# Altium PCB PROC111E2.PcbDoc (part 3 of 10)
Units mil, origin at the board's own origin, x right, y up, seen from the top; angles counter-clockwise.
Board outline 7700 x 2300 mil, 6 copper layers (Top Layer, GND 1, SIG 1, SIG 2, GND 2, Bottom Layer), stack 78.711 mil thick; 767 components, 596 nets, 2755 pads, 1578 vias.
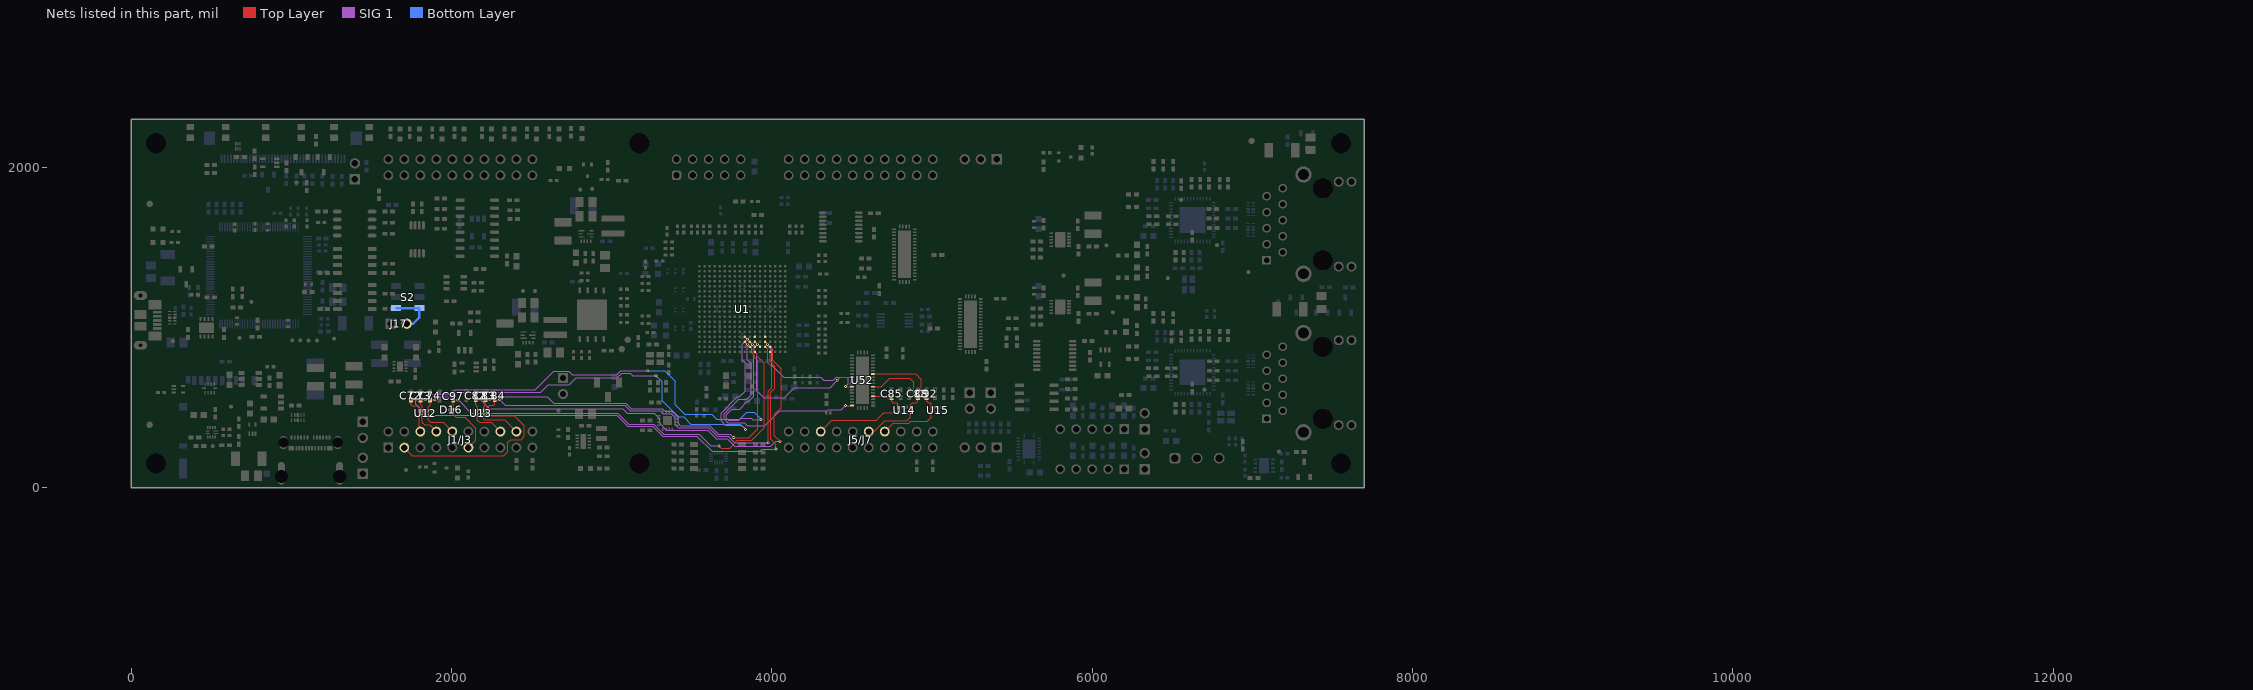
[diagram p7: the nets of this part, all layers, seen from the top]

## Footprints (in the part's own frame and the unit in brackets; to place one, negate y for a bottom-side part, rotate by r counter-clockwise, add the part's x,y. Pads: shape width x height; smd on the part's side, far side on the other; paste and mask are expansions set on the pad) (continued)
"ZCZ (S-PBGA-N324)" [mm] "0.8mm pitch, 15x15mm, Plastic Ball Grid Array"
  round 0.4 smd: A1(0,0) A2(0.8,0) A3(1.6,0) A4(2.4,0) A5(3.2,0) A6(4,0) A7(4.8,0) A8(5.6,0) A9(6.4,0) A10(7.2,0) A11(8,0) A12(8.8,0) A13(9.6,0) A14(10.4,0) A15(11.2,0) A16(12,0) A17(12.8,0) A18(13.6,0) B1(0,-0.8) B2(0.8,-0.8) B3(1.6,-0.8) B4(2.4,-0.8) B5(3.2,-0.8) B6(4,-0.8) B7(4.8,-0.8) B8(5.6,-0.8) B9(6.4,-0.8) B10(7.2,-0.8) B11(8,-0.8) B12(8.8,-0.8) B13(9.6,-0.8) B14(10.4,-0.8) B15(11.2,-0.8) B16(12,-0.8) B17(12.8,-0.8) B18(13.6,-0.8) C1(0,-1.6) C2(0.8,-1.6) C3(1.6,-1.6) C4(2.4,-1.6) C5(3.2,-1.6) C6(4,-1.6) C7(4.8,-1.6) C8(5.6,-1.6) C9(6.4,-1.6) C10(7.2,-1.6) C11(8,-1.6) C12(8.8,-1.6) C13(9.6,-1.6) C14(10.4,-1.6) C15(11.2,-1.6) C16(12,-1.6) C17(12.8,-1.6) C18(13.6,-1.6) D1(0,-2.4) D2(0.8,-2.4) D3(1.6,-2.4) D4(2.4,-2.4) D5(3.2,-2.4) D6(4,-2.4) D7(4.8,-2.4) D8(5.6,-2.4) D9(6.4,-2.4) D10(7.2,-2.4) D11(8,-2.4) D12(8.8,-2.4) D13(9.6,-2.4) D14(10.4,-2.4) D15(11.2,-2.4) D16(12,-2.4) D17(12.8,-2.4) D18(13.6,-2.4) E1(0,-3.2) E2(0.8,-3.2) E3(1.6,-3.2) E4(2.4,-3.2) E5(3.2,-3.2) E6(4,-3.2) E7(4.8,-3.2) E8(5.6,-3.2) E9(6.4,-3.2) E10(7.2,-3.2) E11(8,-3.2) E12(8.8,-3.2) E13(9.6,-3.2) E14(10.4,-3.2) E15(11.2,-3.2) E16(12,-3.2) E17(12.8,-3.2) E18(13.6,-3.2) F1(0,-4) F2(0.8,-4) F3(1.6,-4) F4(2.4,-4) F5(3.2,-4) F6(4,-4) F7(4.8,-4) F8(5.6,-4) F9(6.4,-4) F10(7.2,-4) F11(8,-4) F12(8.8,-4) F13(9.6,-4) F14(10.4,-4) F15(11.2,-4) F16(12,-4) F17(12.8,-4) F18(13.6,-4) G1(0,-4.8) G2(0.8,-4.8) G3(1.6,-4.8) G4(2.4,-4.8) G5(3.2,-4.8) G6(4,-4.8) G7(4.8,-4.8) G8(5.6,-4.8) G9(6.4,-4.8) G10(7.2,-4.8) G11(8,-4.8) G12(8.8,-4.8) G13(9.6,-4.8) G14(10.4,-4.8) G15(11.2,-4.8) G16(12,-4.8) G17(12.8,-4.8) G18(13.6,-4.8) H1(0,-5.6) H2(0.8,-5.6) H3(1.6,-5.6) H4(2.4,-5.6) H5(3.2,-5.6) H6(4,-5.6) H7(4.8,-5.6) H8(5.6,-5.6) H9(6.4,-5.6) H10(7.2,-5.6) H11(8,-5.6) H12(8.8,-5.6) H13(9.6,-5.6) H14(10.4,-5.6) H15(11.2,-5.6) H16(12,-5.6) H17(12.8,-5.6) H18(13.6,-5.6) J1(0,-6.4) J2(0.8,-6.4) J3(1.6,-6.4) J4(2.4,-6.4) J5(3.2,-6.4) J6(4,-6.4) J7(4.8,-6.4) J8(5.6,-6.4) J9(6.4,-6.4) J10(7.2,-6.4) J11(8,-6.4) J12(8.8,-6.4) J13(9.6,-6.4) J14(10.4,-6.4) J15(11.2,-6.4) J16(12,-6.4) J17(12.8,-6.4) J18(13.6,-6.4) K1(0,-7.2) K2(0.8,-7.2) K3(1.6,-7.2) K4(2.4,-7.2) K5(3.2,-7.2) K6(4,-7.2) K7(4.8,-7.2) K8(5.6,-7.2) K9(6.4,-7.2) K10(7.2,-7.2) K11(8,-7.2) K12(8.8,-7.2) K13(9.6,-7.2) K14(10.4,-7.2) K15(11.2,-7.2) K16(12,-7.2) K17(12.8,-7.2) K18(13.6,-7.2) L1(0,-8) L2(0.8,-8) L3(1.6,-8) L4(2.4,-8) L5(3.2,-8) L6(4,-8) L7(4.8,-8) L8(5.6,-8) L9(6.4,-8) L10(7.2,-8) L11(8,-8) L12(8.8,-8) L13(9.6,-8) L14(10.4,-8) L15(11.2,-8) L16(12,-8) L17(12.8,-8) L18(13.6,-8) M1(0,-8.8) M2(0.8,-8.8) M3(1.6,-8.8) M4(2.4,-8.8) M5(3.2,-8.8) M6(4,-8.8) M7(4.8,-8.8) M8(5.6,-8.8) M9(6.4,-8.8) M10(7.2,-8.8) M11(8,-8.8) M12(8.8,-8.8) M13(9.6,-8.8) M14(10.4,-8.8) M15(11.2,-8.8) M16(12,-8.8) M17(12.8,-8.8) M18(13.6,-8.8) N1(0,-9.6) N2(0.8,-9.6) N3(1.6,-9.6) N4(2.4,-9.6) N5(3.2,-9.6) N6(4,-9.6) N7(4.8,-9.6) N8(5.6,-9.6) N9(6.4,-9.6) N10(7.2,-9.6) N11(8,-9.6) N12(8.8,-9.6) N13(9.6,-9.6) N14(10.4,-9.6) N15(11.2,-9.6) N16(12,-9.6) N17(12.8,-9.6) N18(13.6,-9.6) P1(0,-10.4) P2(0.8,-10.4) P3(1.6,-10.4) P4(2.4,-10.4) P5(3.2,-10.4) P6(4,-10.4) P7(4.8,-10.4) P8(5.6,-10.4) P9(6.4,-10.4) P10(7.2,-10.4) P11(8,-10.4) P12(8.8,-10.4) P13(9.6,-10.4) P14(10.4,-10.4) P15(11.2,-10.4) P16(12,-10.4) P17(12.8,-10.4) P18(13.6,-10.4) R1(0,-11.2) R2(0.8,-11.2) R3(1.6,-11.2) R4(2.4,-11.2) R5(3.2,-11.2) R6(4,-11.2) R7(4.8,-11.2) R8(5.6,-11.2) R9(6.4,-11.2) R10(7.2,-11.2) R11(8,-11.2) R12(8.8,-11.2) R13(9.6,-11.2) R14(10.4,-11.2) R15(11.2,-11.2) R16(12,-11.2) R17(12.8,-11.2) R18(13.6,-11.2) T1(0,-12) T2(0.8,-12) T3(1.6,-12) T4(2.4,-12) T5(3.2,-12) T6(4,-12) T7(4.8,-12) T8(5.6,-12) T9(6.4,-12) T10(7.2,-12) T11(8,-12) T12(8.8,-12) T13(9.6,-12) T14(10.4,-12) T15(11.2,-12) T16(12,-12) T17(12.8,-12) T18(13.6,-12) U1(0,-12.8) U2(0.8,-12.8) U3(1.6,-12.8) U4(2.4,-12.8) U5(3.2,-12.8) U6(4,-12.8) U7(4.8,-12.8) U8(5.6,-12.8) U9(6.4,-12.8) U10(7.2,-12.8) U11(8,-12.8) U12(8.8,-12.8) U13(9.6,-12.8) U14(10.4,-12.8) U15(11.2,-12.8) U16(12,-12.8) U17(12.8,-12.8) U18(13.6,-12.8) V1(0,-13.6) V2(0.8,-13.6) V3(1.6,-13.6) V4(2.4,-13.6) V5(3.2,-13.6) V6(4,-13.6) V7(4.8,-13.6) V8(5.6,-13.6) V9(6.4,-13.6) V10(7.2,-13.6) V11(8,-13.6) V12(8.8,-13.6) V13(9.6,-13.6) V14(10.4,-13.6) V15(11.2,-13.6) V16(12,-13.6) V17(12.8,-13.6) V18(13.6,-13.6)
  silkscreen extent -0.8,-14.4 14.4,0.8, body extent -0.7,-14.3 14.3,0.7, height 1

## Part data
C1 C2 C3 C4 C5 C6 C14 C23 C25 C52 C53 C68 C236: library part CMP-0007057-4, "CAP, CERM, 3.3 uF, 10 V, +/- 10%, X7S, 0603", Cap_Case=0603, Manufacturer=TDK, Supplier Part Number 1=445-14256-1-ND, TempCo=X7S, Tolerance_%=10%, Value1="0.004796 ohm", Value2=10V, ValueDisplayed=3.3uF
C7 C8 C9 C10 C11 C12 C13 C15 C16 C17 C18 C24 C26 C27 C28 C34 C35 C36 C37 C38 C48 C69 C72 C73 C74 C75 C78 C79 C80 C81 C82 C83 C84 C85 C86 C87 C88 C90 C91 C92 C93 C94 C95 C96 C97 C98 C117 C119 C121 C125 C127 C131 C133 C165 C176 C194 C196 C198 C202 C204 C208 C210 C237: library part CMP-0006623-2, "CAP, CERM, 0.1 uF, 6.3 V, +/- 10%, X7R, 0402", Cap_Case=0402, Manufacturer=MuRata, Supplier Part Number 1=GRM155R70J104KA01D-ND, TempCo=X7R, Tolerance_%=10%, Value1=Unknown, Value2=6.3V, ValueDisplayed=0.1uF
C19 C20 C21 C22 C29 C30 C31 C32 C39 C40 C41 C42 C44 C45 C46 C47: library part CMP-0093721-1, "Chip Multilayer Ceramic Capacitors for General Purpose, 0201, 1.0uF, X6S, 22%, 20%, 6.3V", Manufacturer=Murata, Operating Temperature Range="-55°C to +105°C", TempCo=22%, Temperature Characteristic=X6S, Tolerance_%=20%, ValueDisplayed=1.0uF
C33 C76 C77 C89: library part CMP-0007498-4, "CAP, CERM, 4.7 uF, 10 V, +/- 20%, X7R, 0603", Cap_Case=0603, Manufacturer=MuRata, TempCo=X7R, Tolerance_%=20%, Value1=Unknown, Value2=10V, ValueDisplayed=4.7uF
C43 C57 C60 C61 C62 C64 C65 C66 C70 C71 C99 C100 C111 C134 C136 C137 C138 C139 C140 C141 C142 C145 C147 C150 C151 C154 C155 C163 C174 C181 C182 C183 C184 C186 C188 C223 C225 C226 C233 C238 C239 C240 C241 C242 C243 C244 C245 C246: library part CMP-0006659-2, "CAP, CERM, 0.1 uF, 25 V, +/- 10%, X7R, 0402", Cap_Case=0402, Manufacturer=MuRata, Supplier Part Number 1=490-10698-1-ND, TempCo=X7R, Tolerance_%=10%, Value1=Unknown, Value2=25V, ValueDisplayed=0.1uF
C49 C50 C51 C54 C55 C56: library part CMP-0064970-1, "CAP, CERM, 0.1 uF, 16 V,+/- 10%, X7R, 0201", Cap_Case=0201, Manufacturer=MuRata, Supplier Part Number 1=81-GRM033Z71C104KE4D, TempCo=X7R, Tolerance_%=10%, Value1=Unknown, Value2=16V, ValueDisplayed=0.1uF
C58 C59 C112 C113 C189 C190: library part CMP-0006375-2, "CAP, CERM, 12 pF, 25 V, +/- 5%, C0G/NP0, 0402", Cap_Case=0402, Manufacturer=MuRata, Supplier Part Number 1=81-GRM1555C1E120JA1D, TempCo=C0G/NP0, Tolerance_%=5%, Value1=Unknown, Value2=25V, ValueDisplayed=12pF
C63 C135 C149 C152: library part CMP-0006658-2, "CAP, CERM, 0.01 uF, 25 V, +/- 10%, X7R, 0402", Cap_Case=0402, Manufacturer=MuRata, Supplier Part Number 1=490-1312-1-ND, TempCo=X7R, Tolerance_%=10%, Value1=Unknown, Value2=25V, ValueDisplayed=0.01uF
C67 C161 C172: library part CMP-0064936-4, "CAP, CERM, 4.7 uF, 16 V,+/- 10%, X7R, 0603", Cap_Case=0603, Manufacturer=MuRata, TempCo=X7R, Tolerance_%=10%, Value1=Unknown, Value2=16V, ValueDisplayed=4.7uF
C101 C106 C108 C110 C248 C249: library part CMP-0007135-4, "CAP, CERM, 0.1 uF, 16 V, +/- 10%, X7R, AEC-Q200 Grade 1, 0603", Cap_Case=0603, Manufacturer=MuRata, Supplier Part Number 1=490-8015-1-ND, TempCo=X7R, Tolerance_%=10%, Value1=Unknown, Value2=16V, ValueDisplayed=0.1uF
C102 C104 C105 C107 C164 C167 C168 C175 C179 C180: library part CMP-0081639-1, "CAP, CERM, 10 µF, 35 V,+/- 10%, X7R, 1210", Cap_Case=1210, Manufacturer=MuRata, Supplier Part Number 1=GRM32ER7YA106KA12K-ND, TempCo=X7R, Tolerance_%=10%, Value1="0.001 ohm", Value2=35V, ValueDisplayed=10µF
C103: library part CMP-0007470-5, "CAP, CERM, 0.1 uF, 100 V, +/- 10%, X7R, 0603", Cap_Case=0603, Manufacturer=MuRata, Supplier Part Number 1=490-6439-1-ND, TempCo=X7R, Tolerance_%=10%, Value1=Unknown, Value2=100V, ValueDisplayed=0.1uF
C109: library part CMP-0006638-1, "CAP, CERM, 1000 pF, 16 V, +/- 10%, X7R, 0402", Cap_Case=0402, Manufacturer=MuRata, Supplier Part Number 1=GRM155R71C102KA01D-ND, TempCo=X7R, Tolerance_%=10%, Value1=Unknown, Value2=16V, ValueDisplayed=1000pF
C114 C122 C128 C191 C199 C205: library part CMP-0007497-5, "CAP, CERM, 10 uF, 10 V, +/- 20%, X7R, 0603", Cap_Case=0603, Manufacturer=MuRata, Supplier Part Number 1=81-GRM188Z71A106MA3D, TempCo=X7R, Tolerance_%=20%, Value1=Unknown, Value2=10V, ValueDisplayed=10uF
C115 C123 C129 C192 C200 C206: library part CMP-0006622-2, "CAP, CERM, 0.01 uF, 6.3 V, +/- 10%, X7R, 0402", Cap_Case=0402, Manufacturer=MuRata, Supplier Part Number 1=GRM155R70J103KA01D-ND, TempCo=X7R, Tolerance_%=10%, Value1=Unknown, Value2=6.3V, ValueDisplayed=0.01uF
C116 C118 C120 C124 C126 C130 C132 C193 C195 C197 C201 C203 C207 C209: library part CMP-0006624-2, "CAP, CERM, 1 uF, 6.3 V, +/- 20%, X7R, 0402", Cap_Case=0402, Manufacturer=MuRata, Supplier Part Number 1=490-9665-1-ND, TempCo=X7R, Tolerance_%=20%, Value1=Unknown, Value2=6.3V, ValueDisplayed=1uF
C143 C144: library part CMP-0087060-3, "Cap Ceramic 8pF 50V C0G 0.5pF SMD 0402 125C Paper T/R", Manufacturer="Murata Electronics North America", TempCo=30ppm/°C
C146 C148 C156 C162 C173 C187 C232: library part CMP-0006349-2, "CAP, CERM, 1 uF, 10 V, +/- 10%, X7S, AEC-Q200 Grade 1, 0402", Cap_Case=0402, Manufacturer=MuRata, Supplier Part Number 1=81-GCM155C71A105KE8D, TempCo=X7S, Tolerance_%=10%, Value1=Unknown, Value2=10V, ValueDisplayed=1uF
C153 C231: library part CMP-0006526-2, "CAP, CERM, 2.2 uF, 16 V, +/- 10%, X6S, 0402", Cap_Case=0402, Manufacturer=MuRata, Supplier Part Number 1=GRM155C81C225KE11D-ND, TempCo=X6S, Tolerance_%=10%, Value1=Unknown, Value2=16V, ValueDisplayed=2.2uF
C157 C158 C169 C170 C185: library part CMP-0008377-2, "CAP, CERM, 22 uF, 10 V, +/- 20%, X7R, 0805", Cap_Case=0805, Manufacturer=MuRata, Supplier Part Number 1=81-GRM21BZ71A226ME5L, TempCo=X7R, Tolerance_%=20%, Value1=Unknown, Value2=10V, ValueDisplayed=22uF
C159 C171: library part CMP-0009221-2, "CAP, CERM, 47 uF, 10 V, +/- 20%, X7R, 1210", Cap_Case=1210, Manufacturer=MuRata, Supplier Part Number 1=490-6543-1-ND, TempCo=X7R, Tolerance_%=20%, Value1=Unknown, Value2=10V, ValueDisplayed=47uF
C160 C177: library part CMP-0007424-4, "CAP, CERM, 0.47 uF, 25 V, +/- 10%, X7R, 0603", Cap_Case=0603, Manufacturer=MuRata, Supplier Part Number 1=490-3291-1-ND, TempCo=X7R, Tolerance_%=10%, Value1=Unknown, Value2=25V, ValueDisplayed=0.47uF
C166 C178: library part CMP-0006706-2, "CAP, CERM, 2700 pF, 100 V, +/- 10%, X7R, 0402", Cap_Case=0402, Manufacturer=MuRata, Supplier Part Number 1=GRM155R72A272KA01D-ND, TempCo=X7R, Tolerance_%=10%, Value1=Unknown, Value2=100V, ValueDisplayed=2700pF
C211 C212 C213 C224: library part CMP-0007144-4, "CAP, CERM, 0.1 uF, 50 V, +/- 10%, X7R, 0603", Cap_Case=0603, Manufacturer=MuRata, Supplier Part Number 1=490-4779-1-ND, TempCo=X7R, Tolerance_%=10%, Value1="0.02 ohm", Value2=50V, ValueDisplayed=0.1uF
C214 C216 C217 C219 C220 C221: library part CMP-0086079-1, "CAP, CERM, 1000 pF, 50 V,+/- 5%, C0G/NP0, AEC-Q200 Grade 1, 0603", Cap_Case=0603, Manufacturer=MuRata, TempCo=C0G/NP0, Tolerance_%=5%, Value2=50V, ValueDisplayed=1000pF
C215 C218: library part CMP-0007171-4, "CAP, CERM, 100 pF, 50 V, +/- 5%, C0G/NP0, 0603", Cap_Case=0603, Manufacturer=MuRata, Supplier Part Number 1=490-1427-1-ND, TempCo=C0G/NP0, Tolerance_%=5%, Value1=Unknown, Value2=50V, ValueDisplayed=100pF
C222: library part CMP-0006361-2, "CAP, CERM, 4700 pF, 50 V, +/- 10%, X7R, AEC-Q200 Grade 1, 0402", Cap_Case=0402, Manufacturer=MuRata, Supplier Part Number 1=490-4915-1-ND, TempCo=X7R, Tolerance_%=10%, Value1=Unknown, Value2=50V, ValueDisplayed=4700pF
C227: library part CMP-0008378-2, "CAP, CERM, 10 uF, 25 V, +/- 10%, X7R, 0805", Cap_Case=0805, Manufacturer=MuRata, Supplier Part Number 1=81-GRM21BZ71E106KE5L, TempCo=X7R, Tolerance_%=10%, Value1=Unknown, Value2=25V, ValueDisplayed=10uF
C228: library part CMP-0006420-2, "CAP, CERM, 15 pF, 50 V, +/- 5%, C0G/NP0, 0402", Cap_Case=0402, Manufacturer=MuRata, Supplier Part Number 1=81-GRM1555C1H150JA1D, TempCo=C0G/NP0, Tolerance_%=5%, Value1=Unknown, Value2=50V, ValueDisplayed=15pF
C229 C230 C234 C235 C247: library part CMP-0009436-2, "CAP, CERM, 1000 pF, 2000 V, +/- 10%, X7R, 1808", Cap_Case=1808, Manufacturer=MuRata, Supplier Part Number 1=490-8145-1-ND, TempCo=X7R, Tolerance_%=10%, Value1=Unknown, Value2=2000V, ValueDisplayed=1000pF
D1: library part CMP-0005599-2, "Diode, TVS, Bi, 6.5 V, SMB", Manufacturer=Littelfuse, Value1=600W
D2 D3 D4 D5 D6 D7 D8 D9 D10 D11 D12 D13 D14: library part CMP-0002894-2, "LED, Green, SMD", Color=green, Manufacturer="Wurth Elektronik", Value1=W, Value2=2V
D15 D16: library part CMP-0073602-3, "1-Channel ESD Protection Diode for USB Type-C and Thunderbolt 3, DPY0002A (X1SON-2)", Alternate Manufacturer="Texas Instruments", Alternate PartNumber=TPD1E01B04DPYT, Operating Temperature Range="-40 to 125 C", Rating=Catalog
DS1 DS2 DS3: library part CMP-0002947-3, "LED, Red, SMD", Color=Red, Manufacturer="Wurth Elektronik", Power_TotalModule=72mW, Value1=0.072W, Value2=2V
FB1 FB2 FB3 FB4 FB5 FB6: library part CMP-0089199-1, "120 Ohms @ 100MHz 1  Ferrite Bead 0603 (1608 Metric) 2A 40mOhm", Digikey Part Number=490-3991-1-ND, Impedance At Frequency="120O @ 100MHz", Manufacturer=Murata, Mouser Part Number=81-BLM18EG121SN1D, Operating Temperature Range="-55°C to +125°C", Tolerance_%=25%
FID1 FID2 FID3: library part CMP-0077181-1, "Fiducial mark.  There is nothing to buy or mount.", Manufacturer=N/A
J1 J9 J10 J13 J14 J15 J16 J17 J18: library part CMP-0054566-1, "Header, 100mil, 2x1, Gold, TH", Color=Black, Current_A=3A, Manufacturer="Sullins Connector Solutions", Supplier Part Number 1=S1011E-02-ND, Voltage_V=1.8kV
J1/J3: library part CMP-0003837-4, "Receptacle, 2.54mm, 10x2, Tin, TH", Alternate Manufacturer="Major League Electronics", Alternate PartNumber=CRD-081413-A-G, Manufacturer=Samtec, Supplier Part Number 1=SAM1204-10-ND
J2: library part CMP-0080007-1, "Conncetor, micro SD, 8+2 Pos, R/A, SMT", Manufacturer="Hirose Electric Co. Ltd.", Supplier Part Number 1=HR1942CT-ND
J2/J4: library part CMP-0078266-4, "Receptacle, 2.54mm, 10x2, Tin, TH", Alternate Manufacturer="Major League Electronics", Alternate PartNumber=CRD-081413-A-G, Manufacturer=Samtec, Supplier Part Number 1=SAM1204-10-ND
J5: library part CMP-0093552-1, "USB-C (USB TYPE-C) USB 3.2 Gen 2 (USB 3.1 Gen 2, Superspeed + (USB 3.1)) Receptacle Connector 24 Position Surface Mount, Right Angle; Through Hole", Digikey Part Number=WM17992CT-ND, Manufacturer=Molex, Mouser Part Number=538-201267-0005, Operating Temperature Range="-40°C to +105°C", Voltage_V=30V
J5/J7: library part CMP-0081070-3, "Receptacle, 2.54mm, 10x2, Tin, TH", Alternate Manufacturer="Major League Electronics", Alternate PartNumber=CRD-081413-A-G, Manufacturer=Samtec, Supplier Part Number 1=SAM1204-10-ND
J6: library part CMP-0093156-1, Current_A=500mA, Digikey Part Number=HFK140CT-ND, Manufacturer=Hirose, Mouser Part Number=798-FH12A-40S0.5SH55, Operating Temperature Range="-40°C to +85°C", Voltage_V=50V
J6/J8: library part CMP-0081071-3, "Receptacle, 2.54mm, 10x2, Tin, TH", Alternate Manufacturer="Major League Electronics", Alternate PartNumber=CRD-081413-A-G, Manufacturer=Samtec, Supplier Part Number 1=SAM1204-10-ND
J7 J8: library part CMP-0093483-1, "RJ45 Connector with 1000 Base-TX Inetgrated Magnetic", Manufacturer=Link-PP, Operating Temperature Range="0°C to +70°C"
J11 J12: library part CMP-0002334-1, "Header, 100mil, 3x1, Gold, TH", Manufacturer="Sullins Connector Solutions", Supplier Part Number 1=S1011E-03-ND
J23: library part CMP-0080722-2, "Header, 2.54mm, 5x2, Gold, TH", Color=Black, Current_A=3A, Manufacturer="Sullins Connector Solutions", Supplier Part Number 1=S2011EC-05-ND, Voltage_V=1kV
J24 J25: library part CMP-0054597-1, "Header, 2.54mm, 5x1, Tin, TH", Color=Black, Current_A=3A, Manufacturer="Sullins Connector Solutions", Supplier Part Number 1=S1012E-05-ND, Voltage_V=1.8kV
J33: library part CMP-0075352-1, "Terminal Block, 3.5mm, 3x1, Tin, R/A, TH", Color=Blue, Current_A=10A, Manufacturer="On-Shore Technology", Supplier Part Number 1=ED2636-ND, Voltage_V=125V
J34: library part CMP-0055311-1, "Receptacle, USB 2.0, Micro B, 5 Position, R/A, SMT", Color=Black, Current_A=1.8A, Manufacturer=Molex, Supplier Part Number 1=WM11263CT-ND, Voltage_V=30V
L1: library part CMP-0003364-1, "Ferrite Bead, 30 ohm @ 100 MHz, 4 A, 0805", Manufacturer=MuRata, Supplier Part Number 1=490-11049-1-ND, Value1="0.014 ohm", Value2=4A, ValueDisplayed="30 ohm"
L2 L3: library part CMP-0064169-1, "Inductor, Shielded, 2.2 uH, 4.7 A, 0.029 ohm, SMD", Manufacturer="Wurth Elektronik", Supplier Part Number 1=732-8232-1-ND, Value1="0.029 ohm", Value2=4.7A, ValueDisplayed=2.2uH
L4: library part CMP-0078538-1, "10µH Semi-Shielded Wirewound Inductor 580mA 816 mOhm Max Nonstandard", Manufacturer="Wurth Electronics"
LBL1: library part CMP-0003625-1, "Thermal Transfer Printable Labels, 0.650\" W x 0.200\" H - 10,000 per roll", Manufacturer=Brady, Supplier Part Number 1=97C5133
Logo1: library part CMP-0074844-1
Logo2: library part CMP-0074838-1, "Texas Instrument Corporate Signature"
Logo3: library part CMP-0074847-1, "FCC_disclaimer"
Logo4: library part CMP-0074769-1
Q1 Q2 Q3: library part CMP-0078819-2, "MOSFET, P-CH, -12 V, -4.3 A, SOT-23", Alternate Manufacturer=None, Manufacturer="Infineon Technologies", Value1="0.05 ohm", Value2="10 nC"
Q4 Q5 Q6 Q7 Q8 Q9: library part CMP-0000947-2, "MOSFET, N-CH, 100 V, 0.17 A, SOT-23", Alternate Manufacturer=None, Manufacturer="Fairchild Semiconductor", Supplier Part Number 1=BSS123NCT-ND, Value1=1, Value2="1.8 nC"
Q10: library part CMP-0000010-3, "MOSFET, P-CH, -20 V, -0.39 A, SOT-323", Alternate Manufacturer=None, Manufacturer="Infineon Technologies", Value1=1
Q11 Q13: library part CMP-0000948-2, "MOSFET, N-CH, 100 V, 0.17 A, SOT-323", Alternate Manufacturer=None, Manufacturer="Diodes Inc.", Supplier Part Number 1=BSS123W-FDICT-ND, Value1=1
R1 R6 R8 R10 R11 R14 R15 R16 R17 R20 R42 R43 R92 R93 R98 R146 R147 R155 R156 R173 R174 R177 R178 R179 R181 R182 R183 R184 R185 R186 R187 R188 R194 R258 R268 R269 R270 R271 R274 R275 R276 R287 R288 R291 R292 R295 R296 R298 R299 R305 R306 R316 R318 R319 R320 R321 R322 R323: library part CMP-0026658-1, "RES, 10.0 k, 1%, 0.1 W, 0402", Manufacturer=Panasonic, Power_W=100mW, Supplier Part Number 1=P10.0KLCT-ND, TempCo="100 ppm/C", Tolerance_%=1%, Value2=0.1W, Value_Code=10k0, ValueDisplayed=10.0k
R2: library part CMP-0026240-2, "RES, 2.67 k, 1%, 0.063 W, AEC-Q200 Grade 0, 0402", Manufacturer=Vishay-Dale, Power_W=63mW, Supplier Part Number 1=541-2.67KLCT-ND, TempCo="100 ppm/C", Tolerance_%=1%, Value2=0.063W, Value_Code=2k67, ValueDisplayed=2.67k
R3 R4 R5 R7 R9 R12 R13 R18 R26 R27 R28 R29 R30 R33 R34 R35 R36 R37 R38 R44 R45 R46 R47 R48 R49 R50 R51 R52 R53 R54 R57 R58 R59 R60 R61 R62 R65 R66 R67 R68 R69 R70 R71 R72 R75 R76 R77 R78 R79 R80 R81 R82 R83 R84 R85 R86 R87 R88 R89 R90 R99 R100 R101 R102 R103 R104 R105 R106 R117 R118 R119 R129 R130 R131 R149 R150 R157 R158 R164 R165 R166 R167 R168 R169 R170 R171 R172 R180 R193 R196 R197 R198 R199 R200 R201 R212 R213 R214 R225 R227 R229 R231 R233 R235 R245 R248 R249 R280 R281 R282 R283 R284 R285 R286 R297 R307: library part CMP-0026992-3, "RES, 0, 5%, 0.1 W, AEC-Q200 Grade 0, 0402", Manufacturer=Panasonic, Power_W=100mW, Supplier Part Number 1=P0.0JCT-ND, TempCo="600 ppm/C", Tolerance_%=5%, Value2=0.1W, Value_Code=0000, ValueDisplayed=0
R19: library part CMP-0026703-1, "RES, 49.9, 1%, 0.1 W, AEC-Q200 Grade 0, 0402", Manufacturer=Panasonic, Power_W=100mW, Supplier Part Number 1=P49.9LCT-ND, TempCo="100 ppm/C", Tolerance_%=1%, Value2=0.1W, Value_Code=49R9, ValueDisplayed=49.9
R21 R22 R23 R24 R25 R96 R97 R256 R278 R289 R290 R293 R294 R300 R304: library part CMP-0078193-1, "RES, 1.0 k, 5%, 0.1 W, AEC-Q200 Grade 0, 0402", Manufacturer=Panasonic, Power_W=100mW, Supplier Part Number 1=P1.0KJCT-ND, TempCo="200 ppm/C", Tolerance_%=5%, Value2=0.1W, Value_Code=1k00, ValueDisplayed=1.0k
R31: library part CMP-0026395-2, "RES, 47.5 k, 1%, 0.063 W, AEC-Q200 Grade 0, 0402", Manufacturer=Vishay-Dale, Power_W=63mW, Supplier Part Number 1=541-47.5KLCT-ND, TempCo="100 ppm/C", Tolerance_%=1%, Value2=0.063W, Value_Code=47k5, ValueDisplayed=47.5k
R32 R253 R254 R255: library part CMP-0021522-3, "RES, 1.00 M, 1%, 0.125 W, AEC-Q200 Grade 0, 0805", Manufacturer=Panasonic, Power_W=125mW, Supplier Part Number 1=P1.00MCCT-ND, TempCo="100 ppm/C", Tolerance_%=1%, Value2=0.125W, Value_Code=1M00, ValueDisplayed=1.00M
R39 R40 R41 R143 R244 R250: library part CMP-0025958-3, "RES, 10.0 k, 1%, 0.063 W, AEC-Q200 Grade 0, 0402", Manufacturer=Vishay-Dale, Power_W=63mW, Supplier Part Number 1=541-10.0KLCT-ND, TempCo="100 ppm/C", Tolerance_%=1%, Value2=0.063W, Value_Code=10k0, ValueDisplayed=10.0k
R55 R56 R63 R64 R73 R74 R95 R175 R176 R189 R190 R191 R192: library part CMP-0026938-5, "RES, 4.7 k, 5%, 0.063 W, AEC-Q200 Grade 0, 0402", Manufacturer=Vishay-Dale, Power_W=63mW, Supplier Part Number 1=541-4.7KJCT-ND, TempCo="200 ppm/C", Tolerance_%=5%, Value2=0.063W, Value_Code=4k70, ValueDisplayed=4.7k
R91: library part CMP-0026873-2, "RES, 200 k, 5%, 0.063 W, AEC-Q200 Grade 0, 0402", Manufacturer=Vishay-Dale, Power_W=63mW, Supplier Part Number 1=541-200KJCT-ND, TempCo="200 ppm/C", Tolerance_%=5%, Value2=0.063W, Value_Code=200k
R94: library part CMP-0026603-2, "RES, 909 k, 1%, 0.063 W, AEC-Q200 Grade 0, 0402", Manufacturer=Vishay-Dale, Power_W=63mW, Supplier Part Number 1=541-909KLCT-ND, TempCo="100 ppm/C", Tolerance_%=1%, Value2=0.063W, Value_Code=909k
R107 R202: library part CMP-0082348-1, "RES, 11.5 k, 1%, 0.1 W, AEC-Q200 Grade 0, 0402", Manufacturer=Panasonic, Power_W=100mW, TempCo="100 ppm/C", Tolerance_%=1%, Value2=0.1W, Value_Code=11k5, ValueDisplayed=11.5k
R108 R109 R110 R111 R112 R113 R114 R115 R116 R120 R121 R122 R123 R124 R125 R126 R127 R128 R153 R203 R204 R205 R206 R207 R208 R209 R210 R211 R215 R216 R217 R218 R219 R220 R221 R222 R223: library part CMP-0026237-2, "RES, 2.49 k, 1%, 0.063 W, AEC-Q200 Grade 0, 0402", Manufacturer=Vishay-Dale, Power_W=63mW, Supplier Part Number 1=541-2.49KLCT-ND, TempCo="100 ppm/C", Tolerance_%=1%, Value2=0.063W, Value_Code=2k49, ValueDisplayed=2.49k
R132: library part CMP-0026993-2, "RES, 100, 5%, 0.1 W, AEC-Q200 Grade 0, 0402", Manufacturer=Panasonic, Power_W=100mW, Supplier Part Number 1=P100JCT-ND, TempCo="200 ppm/C", Tolerance_%=5%, Value2=0.1W, Value_Code=100R, ValueDisplayed=100
R133 R134 R135 R324 R325 R326 R327 R328 R329 R330 R331 R332 R333 R334 R335: library part CMP-0026299-2, "RES, 33.2, 1%, 0.063 W, AEC-Q200 Grade 0, 0402", Manufacturer=Vishay-Dale, Power_W=63mW, Supplier Part Number 1=541-33.2LCT-ND, TempCo="100 ppm/C", Tolerance_%=1%, Value2=0.063W, Value_Code=33R2, ValueDisplayed=33.2
R136 R137: library part CMP-0078210-2, "RES, 330 k, 1%, 0.063 W, AEC-Q200 Grade 0, 0402", Manufacturer=Vishay-Dale, Power_W=63mW, Supplier Part Number 1=541-330KLCT-ND, TempCo="100 ppm/C", Tolerance_%=1%, Value2=0.063W, Value_Code=330k
R138 R139 R140 R141 R144 R261 R308 R309 R310 R311 R312: library part CMP-0026071-3, "RES, 1.00 k, 1%, 0.063 W, AEC-Q200 Grade 0, 0402", Manufacturer=Vishay-Dale, Power_W=63mW, Supplier Part Number 1=541-1.00KLCT-ND, TempCo="100 ppm/C", Tolerance_%=1%, Value2=0.063W, Value_Code=1k00, ValueDisplayed=1.00k
R142: library part CMP-0026404-2, "RES, 49.9, 1%, 0.063 W, AEC-Q200 Grade 0, 0402", Manufacturer=Vishay-Dale, Power_W=63mW, Supplier Part Number 1=541-49.9LCT-ND, TempCo="100 ppm/C", Tolerance_%=1%, Value2=0.063W, Value_Code=49R9, ValueDisplayed=49.9
R145: library part CMP-0026413-2, "RES, 4.87 k, 1%, 0.063 W, AEC-Q200 Grade 0, 0402", Manufacturer=Vishay-Dale, Power_W=63mW, Supplier Part Number 1=541-4.87KLCT-ND, TempCo="100 ppm/C", Tolerance_%=1%, Value2=0.063W, Value_Code=4k87, ValueDisplayed=4.87k
R148 R160: library part CMP-0021602-3, "RES, 18.2 k, 1%, 0.125 W, AEC-Q200 Grade 0, 0805", Manufacturer=Panasonic, Power_W=125mW, Supplier Part Number 1=P18.2KCCT-ND, TempCo="100 ppm/C", Tolerance_%=1%, Value2=0.125W, Value_Code=18k2, ValueDisplayed=18.2k
R151: library part CMP-0026336-2, "RES, 3.57 k, 1%, 0.063 W, AEC-Q200 Grade 0, 0402", Manufacturer=Vishay-Dale, Power_W=63mW, Supplier Part Number 1=541-3.57KLCT-ND, TempCo="100 ppm/C", Tolerance_%=1%, Value2=0.063W, Value_Code=3k57, ValueDisplayed=3.57k
R152: library part CMP-0026093-3, "RES, 1.69 k, 1%, 0.063 W, AEC-Q200 Grade 0, 0402", Manufacturer=Vishay-Dale, Power_W=63mW, Supplier Part Number 1=541-1.69KLCT-ND, TempCo="100 ppm/C", Tolerance_%=1%, Value2=0.063W, Value_Code=1k69, ValueDisplayed=1.69k
R154 R161 R163: library part CMP-0026414-2, "RES, 4.99 k, 1%, 0.063 W, AEC-Q200 Grade 0, 0402", Manufacturer=Vishay-Dale, Power_W=63mW, Supplier Part Number 1=541-4.99KLCT-ND, TempCo="100 ppm/C", Tolerance_%=1%, Value2=0.063W, Value_Code=4k99, ValueDisplayed=4.99k
R159: library part CMP-0026097-2, "RES, 1.87 k, 1%, 0.063 W, AEC-Q200 Grade 0, 0402", Manufacturer=Vishay-Dale, Power_W=63mW, Supplier Part Number 1=541-1.87KLCT-ND, TempCo="100 ppm/C", Tolerance_%=1%, Value2=0.063W, Value_Code=1k87, ValueDisplayed=1.87k
R162: library part CMP-0026028-3, "RES, 15.4 k, 1%, 0.063 W, AEC-Q200 Grade 0, 0402", Manufacturer=Vishay-Dale, Power_W=63mW, Supplier Part Number 1=541-15.4KLCT-ND, TempCo="100 ppm/C", Tolerance_%=1%, Value2=0.063W, Value_Code=15k4, ValueDisplayed=15.4k
R195: library part CMP-0026659-2, "RES, 100 k, 1%, 0.1 W, 0402", Manufacturer=Panasonic, Power_W=100mW, TempCo="100 ppm/C", Tolerance_%=1%, Value2=0.1W, Value_Code=100k
R224 R226 R228 R230 R232 R234: library part CMP-0026878-3, "RES, 220, 5%, 0.063 W, AEC-Q200 Grade 0, 0402", Manufacturer=Vishay-Dale, Power_W=63mW, Supplier Part Number 1=541-220JCT-ND, TempCo="200 ppm/C", Tolerance_%=5%, Value2=0.063W, Value_Code=220R, ValueDisplayed=220
R236 R237 R238 R239 R240 R241 R242 R243: library part CMP-0026702-1, "RES, 49.9 k, 1%, 0.1 W, AEC-Q200 Grade 0, 0402", Manufacturer=Panasonic, Power_W=100mW, Supplier Part Number 1=P49.9KLCT-ND, TempCo="100 ppm/C", Tolerance_%=1%, Value2=0.1W, Value_Code=49k9, ValueDisplayed=49.9k
R246 R247: library part CMP-0026491-2, "RES, 61.9, 1%, 0.063 W, AEC-Q200 Grade 0, 0402", Manufacturer=Vishay-Dale, Power_W=63mW, Supplier Part Number 1=541-61.9LCT-ND, TempCo="100 ppm/C", Tolerance_%=1%, Value2=0.063W, Value_Code=61R9, ValueDisplayed=61.9
R251: library part CMP-0026437-2, "RES, 51.1 k, 1%, 0.063 W, AEC-Q200 Grade 0, 0402", Manufacturer=Vishay-Dale, Power_W=63mW, Supplier Part Number 1=541-51.1KLCT-ND, TempCo="100 ppm/C", Tolerance_%=1%, Value2=0.063W, Value_Code=51k1, ValueDisplayed=51.1k
R252: library part CMP-0078244-2, "RES, 30.0 k, 1%, 0.063 W, AEC-Q200 Grade 0, 0402", Manufacturer=Vishay-Dale, Power_W=63mW, Supplier Part Number 1=541-30.0KLCT-ND, TempCo="100 ppm/C", Tolerance_%=1%, Value2=0.063W, Value_Code=30k0, ValueDisplayed=30.0k
R257: library part CMP-0026704-1, "RES, 510, 1%, 0.1 W, 0402", Manufacturer=Panasonic, Power_W=100mW, Supplier Part Number 1=P510LCT-ND, TempCo="100 ppm/C", Tolerance_%=1%, Value2=0.1W, Value_Code=510R, ValueDisplayed=510
R259 R260 R265 R302 R314: library part CMP-0078194-1, "RES, 360, 5%, 0.1 W, AEC-Q200 Grade 0, 0402", Manufacturer=Panasonic, Power_W=100mW, Supplier Part Number 1=P360JCT-ND, TempCo="200 ppm/C", Tolerance_%=5%, Value2=0.1W, Value_Code=360R, ValueDisplayed=360
R262 R263 R264 R266 R267 R273 R277 R279: library part CMP-0026680-1, "RES, 220, 1%, 0.1 W, AEC-Q200 Grade 0, 0402", Manufacturer=Panasonic, Power_W=100mW, Supplier Part Number 1=P220LCT-ND, TempCo="100 ppm/C", Tolerance_%=1%, Value2=0.1W, Value_Code=220R, ValueDisplayed=220
R272 R303 R317: library part CMP-0078212-1, "RES, 510, 5%, 0.1 W, AEC-Q200 Grade 0, 0402", Manufacturer=Panasonic, Power_W=100mW, Supplier Part Number 1=P510JCT-ND, TempCo="200 ppm/C", Tolerance_%=5%, Value2=0.1W, Value_Code=510R, ValueDisplayed=510
R313 R315: library part CMP-0025998-3, "RES, 130, 1%, 0.063 W, AEC-Q200 Grade 0, 0402", Manufacturer=Vishay-Dale, Power_W=63mW, Supplier Part Number 1=541-130LCT-ND, TempCo="100 ppm/C", Tolerance_%=1%, Value2=0.063W, Value_Code=130R, ValueDisplayed=130
S1: library part CMP-0002139-2, "Switch, Slide, SPDT  100mA, SMT", CurrentRating_mA=100A, Manufacturer="Copal Electronics", Supplier Part Number 1=CAS120JCT-ND
S2: library part CMP-0002233-1, "Switch, Dual SPDT,  2 Pos, 0.1A, 6VDC, SMD", CurrentRating_mA=100A, Manufacturer="Copal Electronics", Supplier Part Number 1=CASD20JCT-ND
SH-J1 SH-J2 SH-J3 SH-J4 SH-J5 SH-J6 SH-J7: library part CMP-0003761-2, "Shunt, 2.54mm, Gold, Black", Manufacturer="Wurth Elektronik", Supplier Part Number 1=732-2678-ND
SW1: library part CMP-0093176-1, "Dip Switch SPST 4 Position Surface Mount Slide (Standard) Actuator 25mA 24VDC", Coil Resistance_ohm=100mO, Contact Current Rating=25mA, Digikey Part Number=732-3854-1-ND, Manufacturer=Wurth, Mouser Part Number=710-416131160804, Operating Temperature Range="-40°C to +85°C"
SW2 SW3 SW4: library part CMP-0093456-1, "Tactile Switch SPST-NO Side Actuated Surface Mount, Right Angle", Coil Resistance_ohm=100mO, Contact Current Rating=50mA, Digikey Part Number=732-7057-1-ND, Manufacturer="Wurth Electronics", Mouser Part Number=710-434351045816, Operating Force=160gf, Operating Temperature Range="-40°C to +85°C"
TP1 TP2: library part CMP-0003825-1, "1mm Test Point, SMT", Manufacturer=Any
TP3 TP4 TP5 TP6 TP7 TP8 TP9 TP10 TP11 TP12 TP13 TP14 TP15 TP16 TP17 TP18 TP19 TP20 TP21 TP22 TP23 TP24 TP25 TP26 TP27 TP28 TP29 TP30: library part CMP-0078143-3, "TEST POINT.  No entry in BOM.", Manufacturer=N/A
U1: "Sitara AM263x MCU (Pinlist Revision 0.96, Pinmux 0.98)", Manufacturer="Texas Instruments", PartNumber=XAM2634AOLFGMZCZQ
U2: library part CMP-0051219-1, "Single 3-Input Positive-AND Gate, DBV0006A, LARGE T&R", F @ Nom Voltage(Max)(Mhz)=150, Generic Part Number=SN74LVC1G11, ICC @ Nom Voltage(Max)(mA)=0.01, Manufacturer="Texas Instruments", Operating Temperature Range(C)="-40 to 125,-40 to 85", Rating=Catalog, tpd @ Nom Voltage(Max)(ns)=20,7.8,6.2,4.6, Voltage(Nom)(V)=1.8,2.5,3.3,5
U3: library part CMP-0043157-2, "Low-Voltage 8-Bit I2C and SMBus I/O Expander, 1.65 to 5.5 V, -40 to 85 degC, 16-pin QFN (RGT), Green (RoHS & no Sb/Br)", 5V Tolerant I/O=Yes, Manufacturer="Texas Instruments", Max Frequency(kHz)=400
U4: library part CMP-0066450-2, "4-Bit Dual-Supply Bus Transceiver with Configurable Voltage-Level Shifting and 3-State Outputs, RSV0016A (UQFN-16)", Alternate Manufacturer="Texas Instruments"
U5 U9 U47: library part CMP-0051588-2, "Single 2-Input Positive-AND Gate, DBV0005A, LARGE T&R", Alternate Manufacturer="Texas Instruments", F @ Nom Voltage(Max)(Mhz)=150, Generic Part Number=SN74LVC1G08, ICC @ Nom Voltage(Max)(mA)=0.01, Operating Temperature Range(C)="-40 to 125,-40 to 85", Rating=Catalog, tpd @ Nom Voltage(Max)(ns)=4.5,6,4,5, Voltage(Nom)(V)=1.8,2.5,3.3,5
U6: library part CMP-0051704-3, "Single Schmitt-Trigger Buffer, DCK0005A, LARGE T&R", F @ Nom Voltage(Max)(Mhz)=150, Generic Part Number=SN74LVC1G17, ICC @ Nom Voltage(Max)(mA)=0.01, Manufacturer="Texas Instruments", Operating Temperature Range(C)="-40 to 125,-40 to 85", Rating=Catalog, tpd @ Nom Voltage(Max)(ns)=11,6.5,5.5,5, Voltage(Nom)(V)=1.8,2.5,3.3,5
U7: library part CMP-0093537-1, "FLASH - NOR Memory IC 128Mb (16M x 8) SPI - Quad I/O 133 MHz 8-WSON (6x8)", Digikey Part Number=1274-1178-ND, Frequency_Fixed=133MHz, Manufacturer="Cypress Semiconductor", Max Supply Voltage=3.6V, Min Supply Voltage=1.65V, Mouser Part Number=797-25FL128SAGNFI000, Nominal Supply Current=16-100mA, Operating Temperature Range="-40°C to +85°C"
U8: library part CMP-0081995-1, "5.5V, 2A, 52mO Automotive High-Side Load Switch with Adjustable Rise Time & Quick Output Discharge, DBV0006A (SOT-23-6)", Alternate Manufacturer="Texas Instruments", Alternate PartNumber=TPS22918TDBVRQ1, Operating Temperature Range="-40 to 105 C", Rating=Automotive
U10: library part CMP-0043096-2, "Low-Capacitance + / - 15 kV ESD-Protection Array for High-Speed Data Interfaces, 2 Channels, -40 to +85 degC, 5-pin SOT (DRL), Green (RoHS & no Sb/Br)", Breakdown Voltage(Min)(V)=11, IO Capacitance(Typ)(pF)=1.5, IO Leakage Current(nA)=1, Manufacturer="Texas Instruments"
U11: library part CMP-0043123-1, "Low-Capacitance + / - 15 kV ESD Protection Array for High-Speed Data Interfaces, 6 Channels, -40 to +85 degC, 10-pin UQFN (RSE), Green (RoHS & no Sb/Br)", Breakdown Voltage(Min)(V)=11, IO Capacitance(Typ)(pF)=1.5, IO Leakage Current(nA)=1, Manufacturer="Texas Instruments"
U12 U13 U14 U15 U20 U44: library part CMP-0073612-3, "4-Channel ESD Protection Diode for USB Type-C and HDMI 2.0, DQA0010A (USON-10)", Alternate Manufacturer="Texas Instruments"
U16: library part CMP-0005327-2, "1024-Kb I2C CMOS Serial EEPROM, SOIC-8", Manufacturer="ON Semiconductor", Supplier Part Number 1=CAT24M01WI-GT3OSTR-ND
U17: library part CMP-0067419-2, "2-Channel, 2:1 Analog Switch with Low On-State Resistance (1ohm) and Powered Off Protection, DGS0010A (VSSOP-10)", Alternate Manufacturer="Texas Instruments", Alternate PartNumber=TS5A23159DGST, Operating Temperature Range="-40 to 85 C", Rating=Catalog
U18: library part CMP-0073635-2, "USB Type-C Configuration Channel Logic and Port Control, RWB0012A (X2QFN-12)", Alternate Manufacturer="Texas Instruments", Operating Temperature Range="-40 to 85 C", Rating=Catalog
U19: library part CMP-0073678-3, "5.5V, 4A, 16mO Automotive Load Switch With Adjustable Rise Time and Optional Quick Output Discharge, DSG0008B (WSON-8)", Alternate Manufacturer="Texas Instruments", Alternate PartNumber=TPS22965TDSGTQ1
U21: library part CMP-0051530-2, "Single 2-Input Positive-NOR Gate, DRL0005A, LARGE T&R", Alternate Manufacturer="Texas Instruments", F @ Nom Voltage(Max)(Mhz)=75, Generic Part Number=SN74AHC1G02, ICC @ Nom Voltage(Max)(mA)=0.01, Operating Temperature Range(C)="-40 to 125,-40 to 85", Rating=Catalog, tpd @ Nom Voltage(Max)(ns)=11.4,7.5, Voltage(Nom)(V)=3.3,5
U22 U37: library part CMP-0091377-1, "1/1 Transceiver Ethernet 48-VQFN (7x7)", Digikey Part Number=296-53377-1-ND, Manufacturer="Texas Instruments", Max Supply Voltage=3.45V, Min Supply Voltage=990mV, Mouser Part Number=595-DP83869HMRGZT, Operating Temperature Range="-40°C to +125°C"
U23 U50 U52: library part CMP-0093539-2, "IC MUX/DEMUX DDR3 1:2 42WQFN", Digikey Part Number=296-28307-1-ND, Manufacturer="Texas Instruments", Max Supply Voltage=3.6V, Min Supply Voltage=3V, Mouser Part Number=595-TS3DDR3812RUAR, Nominal Supply Current=300uA, On State Resistance=8O, Operating Temperature Range="-40°C to +85°C"
U24: library part CMP-0029856-2, "Tiva C Series Microcontroller, 1024 KB Flash, 256 KB SRAM, 12 Bit, 20 Channels, -40 to 105 degC, 128-Pin TQFP (PDT), Green (RoHS & no Sb/Br), Tray", Manufacturer="Texas Instruments", Temperature Range="-40 to 105 degC"
U25: library part CMP-0029369-1, "25 Mbps Dual Channels, 2 / 0, Digital Isolator, 3.3 V / 5 V, -40 to +125 degC, 8-pin SOIC (D), Green (RoHS & no Sb/Br)", Insulation Rating(VRMS)=2500, Manufacturer="Texas Instruments", Rating=Catalog, Supply Voltage(s)(V)="3.3, 5"
U26 U27: library part CMP-0076059-2, "High Speed, Robust EMC Dual-Channel Digital Isolator, D0008B (SOIC-8)", Alternate Manufacturer="Texas Instruments", Alternate PartNumber=ISO7721D, Operating Temperature Range="-55 to 125 C", Rating=Catalog
U28: library part CMP-0033001-1, "Precision Micropower Shunt Voltage Reference, 0.5% accuracy, 2.5 V, 15 ppm / degC, 15 mA, -40 to 125 degC, 3-pin SOT-23 (DBZ), Green (RoHS & no Sb/Br)", Manufacturer="Texas Instruments", Rating=Catalog, Temp Coeff(Max)(ppm/ degree C)=100, Temp Coeff(Typ)(ppm/ degree C)=15
U29 U32: library part CMP-0089785-1, "3V to 17V, 3A Micro Noise (20µVRMS) and Micro Ripple (200µVPP) buck converter", Manufacturer="Texas Instruments", Max Supply Voltage=17V, Min Supply Voltage=3V, Nominal Supply Current=5mA, Operating Temperature Range="-40°C to +150°C", Output Voltage=0.8-5.5V, Switching Frequency=1/2.2MHz
U30 U31: library part CMP-0036365-5, "Single Output LDO, 1.5A, Adj. (0.8 to 3.6V), Programmable Soft-Start, DRC0010J (VSON-10)", Manufacturer="Texas Instruments", Operating Temperature Range="-40 to 125 C", Power Good=TRUE, Rating=Catalog
U33: library part CMP-0051392-2, "Single Buffer/Driver With Open-Drain Output, DCK0005A, SMALL T&R", F @ Nom Voltage(Max)(Mhz)=150, Generic Part Number=SN74LVC1G07, ICC @ Nom Voltage(Max)(mA)=0.01, Manufacturer="Texas Instruments", Operating Temperature Range(C)="-40 to 125,-40 to 85", Rating=Catalog, tpd @ Nom Voltage(Max)(ns)=8.6,6,4.7,4, Voltage(Nom)(V)=1.8,2.5,3.3,5
U34: library part CMP-0051904-4, "Dual Schmitt-Trigger Buffer, DSF0006A, LARGE T&R", F @ Nom Voltage(Max)(Mhz)=150, Generic Part Number=SN74LVC2G17, ICC @ Nom Voltage(Max)(mA)=0.01, Manufacturer="Texas Instruments", Operating Temperature Range(C)="-40 to 125,-40 to 85", Rating=Catalog, tpd @ Nom Voltage(Max)(ns)=9.3,5.7,5.4,4.3, Voltage(Nom)(V)=1.8,2.5,3.3,5
U35: library part CMP-0076016-2, "Level-Translating I2C Bus Repeater, DGK0008A (VSSOP-8)", Alternate Manufacturer="Texas Instruments"
U36: library part CMP-0067107-3, "28V, 0.5A Step-Down Converter with SNOOZE Mode, DQC0010A (WSON-10)", Alternate Manufacturer="Texas Instruments", Alternate PartNumber=TPS62177DQCT
U38 U39 U40 U41: library part CMP-0073613-3, "4-Channel Ultra-Low-Capacitance IEC ESD Protection Diode, DQA0010A (USON-10)", Alternate Manufacturer="Texas Instruments"
U42: library part CMP-0079884-2, "Automotive High Speed CAN Transceiver, DRB0008J (VSON-8)", Alternate Manufacturer="Texas Instruments", Alternate PartNumber=TCAN1044VDRBRQ1
U43: library part CMP-0074359-2, "8-Bit Bidirectional Voltage-Level Shifter with Auto Direction Sensing and +/-15-kV ESD Protect, RGY0020A (VQFN-20)", Alternate Manufacturer="Texas Instruments"
U45: library part CMP-0036402-3, "Single Output High PSRR LDO, 1 A, Adjustable 1.2 to 5.5 V Output, 2.7 to 5.5 V Input, 8-pin SON (DRB), -40 to 125 degC, Green (RoHS & no Sb/Br)", Manufacturer="Texas Instruments"
U46: library part CMP-0051684-3, "Single Inverter, DCK0005A, LARGE T&R", F @ Nom Voltage(Max)(Mhz)=150, Generic Part Number=SN74LVC1G04, ICC @ Nom Voltage(Max)(mA)=0.01, Manufacturer="Texas Instruments", Operating Temperature Range(C)="-40 to 125,-40 to 85", Rating=Catalog, tpd @ Nom Voltage(Max)(ns)=7.5,5.2,4.2,3.7, Voltage(Nom)(V)=1.8,2.5,3.3,5
U48: library part CMP-0044782-1, "8-Bit LED Driver with I2C Interface, D0016A, TUBE", Generic Part Number=TPIC2810, Manufacturer="Texas Instruments", Operating Temperature Range(C)="-40 to 125", Rating=Catalog
U49 U51: library part CMP-0076540-1, "4-Bit One-of-2 FET Multiplexer/Demultiplexer 2.5-V/3.3-V Low-Voltage, High-Bandwidth Bus Switch, PW0016A (TSSOP-16)", Alternate Manufacturer="Texas Instruments"
Y1: library part CMP-0084811-1, "Crystal, 25 MHz, 10 ppm, 4 pF, SMD", Frequency Stability="20 ppm", Frequency Tolerance="10 ppm", Frequency_Fixed=25MHz, Load Capacitance="4 pF", Manufacturer="Abracon Corporation", PartNumber=ABM10W-25.0000MHZ-8-K1Z-T3
Y2 Y4: library part CMP-0084811-1, "Crystal, 25 MHz, 10 ppm, 4 pF, SMD", Frequency_Fixed=25MHz, Frequency Stability="20 ppm", Frequency Tolerance="10 ppm", Load Capacitance="4 pF", Manufacturer="Abracon Corporation"
Y3: library part CMP-0004635-3, "Crystal, 16 MHz, 8pF, SMD", Frequency_Fixed=16MHz, Frequency Stability=+/-30ppm, Manufacturer=NDK, Supplier Part Number 1=644-1157-1-ND
ZZ1: library part CMP-0003616-3
ZZ2: library part CMP-0077236-1
ZZ3: library part CMP-0077237-1
ZZ4: library part CMP-0077238-1

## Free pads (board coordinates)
  round 65.36 on Mech16: 1(-281.58,414) 1(249.42,53) 1(1196.42,275) 1(1203.42,-873) 1(1504.42,253) 1(2385.42,-444)
  round 15.62 on Mech16: 1(3783.19,-279.05)

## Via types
v1: diameter 18, hole 8, Top Layer to Bottom Layer, tented both sides, 1474 vias
v2: diameter 19.68, hole 7.87, Top Layer to Bottom Layer, tented both sides, 104 vias

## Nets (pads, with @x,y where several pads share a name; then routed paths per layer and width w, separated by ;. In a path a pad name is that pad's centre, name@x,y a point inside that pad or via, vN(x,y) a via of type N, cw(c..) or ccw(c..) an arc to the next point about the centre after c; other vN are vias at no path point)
ADC_EXT_VREF: J17.2 S2.3 S2.6 | length 299.9
  Bottom Layer w15: S2.6@1651.87,1121.1 S2.3@1797.54,1121.1 1797.54,1061.29 1760.02,1023.77 J17.2@1718.62,1023.77
AM263_ADC0_AIN0: C72.1 J1/J3.23 U1.V15 U12.1 U12.10 | length 3318.4
  Top Layer w4: 3988.08,815.87 U1.V15@3988.08,847.36
  Top Layer w5.3: v1(1775,548.33) C72.1@1745,548.33 1745,519.48 1753.65,510.82 1781.73,510.82 1795.63,496.93 U12.10@1795.63,480.91 U12.1@1795.63,448.04 1795.63,358.54 J1/J3.23@1804.17,350 ; 3988.08,815.87 3988.08,787.62 4017.81,757.88 4017.81,620.54 3992.7,595.43 3992.7,302.3 4025,270 v1(4025,240.62)
  SIG 1 w4.75: v1(1775,548.33) 1775,520 1844.48,450.52 3031.1,450.52 3099.1,382.52 3256.48,382.52 3318,321 3531.04,321 3626.14,225.9 3925.58,225.9 3940.3,240.62 v1(4025,240.62)
AM263_ADC0_AIN1: C82.1 J1/J3.28 U1.U15 U13.2 U13.9 | length 3004.4
  Top Layer w4: U1.U15@3988.08,878.86 4003.83,863.11 4003.83,815.87
  Top Layer w5.3: v1@2180,548.85 C82.1@2150,548.85 2150,516.35 2160.31,506.03 U13.9@2160.31,481.44 U13.2@2160.31,448.56 2160.31,421.62 2175,406.94 2247.24,406.94 J1/J3.28@2304.17,350 ; 4003.98,815.87 4003.98,794.2 4056.86,741.32 4056.86,498.59 4015,456.73 4015,323.76 v1(4050,288.76)
  SIG 1 w4.75: v1(2180,548.85) 2235.58,493.27 3066.73,493.27 3095.75,464.25 3263.62,464.25 3298,429.87 3298,400.5 3340.85,357.65 3599.47,357.65 3652.12,305 3721.32,305 3766.67,259.65 3993.32,259.65 4022.43,288.76 v1(4050,288.76)
AM263_ADC0_AIN2: U1.T14 U52.32 | length 790.2
  Top Layer w5.3: v1(4458.39,630.63) U52.32@4500.04,630.63
  Top Layer w10: U1.T14@3956.58,910.35 v1(3972.33,894.61)
  SIG 1 w4.75: v1(3972.33,894.61) 3972.33,885.08 3999.43,857.98 3999.43,762.5 4073.08,688.86 4305.29,688.86 4323.32,670.83 4381.38,670.83 4399.8,689.25 4465.75,689.25 4477.03,677.97 4477.03,649.27 v1(4458.39,630.63)
AM263_ADC0_AIN2_LIN1_TXD: C88.1 J5/J7.66 U14.5 U14.6 U52.7 | length 857.5
  Top Layer w5.3: J5/J7.66@4604.17,350 4635.87,350 4704.19,418.33 4842.8,418.33 4864.37,439.89 U14.5@4864.37,467.68 U14.6@4864.37,500.55 4864.37,516.12 4877.56,529.31 4902.1,529.31 4910,537.21 4910,560.42 C88.1@4911.11,561.53 4893.47,561.53 4885,570 4885,658.91 4861.58,682.33 4734.12,682.33 4682.42,630.63 U52.7@4629.96,630.63
AM263_ADC0_AIN3: C84.1 J1/J3.2 U1.U14 U13.5 U13.6 | length 3787.4
  Top Layer w4: U1.U14@3956.58,878.86 3972.4,863.04 3972.4,816.09 3972.18,815.87
  Top Layer w5.3: J1/J3.2@1704.17,250 1754.17,200 2325,200 2350,225 2350,282.66 2367.34,300 2434.55,300 2453.98,319.43 2453.98,386.33 2391.75,448.56 U13.5@2219.37,448.56 U13.6@2219.37,481.44 2219.37,494.53 2238.22,513.38 2261.62,513.38 2269,520.76 C84.1@2269,548.85 v1@2299,548.85 ; 3972.18,815.87 3972.18,780.46 3999.52,753.11 3999.52,624.73 3976.8,602.01 v1(3976.8,280)
  SIG 1 w4.75: v1(2299,548.85) 2334.35,513.5 3080.59,513.5 3115.59,478.5 3301.5,478.5 3319.1,460.9 3371.67,460.9 3395,437.57 3395,392.52 3415.02,372.5 3604.77,372.5 3658.02,319.25 3727.22,319.25 3766.47,280 v1(3976.8,280)
AM263_ADC0_AIN4: U1.U13
AM263_ADC0_AIN5: U1.R14
AM263_ADC1_AIN0: C73.1 J1/J3.24 U1.T11 U12.2 U12.9 | length 3552.9
  Top Layer w5.3: v1(1835,548.33) C73.1@1805,548.33 1805,515.82 1815.31,505.51 U12.9@1815.31,480.91 U12.2@1815.31,448.04 1815.31,405.72 1830,391.04 1863.14,391.04 J1/J3.24@1904.17,350
  Top Layer w10: U1.T11@3862.09,910.35 v1(3877.84,894.61)
  SIG 1 w4: v1(3877.84,894.61) 3875.16,891.93 3875.16,885.43 3875,885.26 3875,841.84 3885,831.84 3885,815.87
  SIG 1 w4.75: v1(1835,548.33) 1868.5,581.83 1994.64,581.83 2023.66,610.85 2520.85,610.85 2637.19,727.19 2731.8,727.19 2753.25,705.75 3030.87,705.75 3055,729.88 v1(3224.39,729.88) ; 3885,815.87 3885,569.25 3853.39,537.64 3844.74,537.64 3797.1,490 3749.68,490 3715.75,456.08 3715.75,431.53 3728.28,419 3793.51,419 3807.48,432.96 3870.67,432.96 3878.63,425 v1(3931.68,425)
  Bottom Layer w5.3: v1(3224.39,729.88) 3330.65,729.88 3395.48,665.06 3395.48,516.52 3454.23,457.77 3624.52,457.77 3655.64,426.64 3799.33,426.64 3843.06,470.38 3888.09,470.38 3931.68,426.78 v1(3931.68,425)
AM263_ADC1_AIN1: C83.1 J1/J3.29 U1.U11 U13.4 U13.7 | length 2751.7
  Top Layer w4: U1.U11@3862.09,878.86 3877.84,863.11 3877.84,837.51 3889.34,826 3889.34,815
  Top Layer w5.3: v1@2240,548.85 C83.1@2210,548.85 2210,515.31 2199.68,505 U13.7@2199.68,481.44 U13.4@2199.68,448.56 2199.68,428.15 2205,422.84 2331.34,422.84 J1/J3.29@2404.17,350 ; v1(3761.09,312.6) 3854.57,312.6 3909.82,367.86 3909.82,794.52 3889.34,815
  SIG 1 w4.75: v1(2240,548.85) 2259.25,568.1 2595.45,568.1 2635.8,527.75 3086.49,527.75 3121.49,492.75 3315.1,492.75 3332.7,475.15 3377.57,475.15 3413.27,439.45 3413.27,400.89 3426.5,387.66 3610.31,387.66 3664.47,333.5 3740.19,333.5 v1(3761.09,312.6)
AM263_ADC1_AIN2: U1.T12 U52.29 | length 993.2
  Top Layer w5.3: v1(4407.78,670) 4427.46,689.69 U52.29@4500.04,689.68
  Top Layer w10: U1.T12@3893.59,910.35 v1(3909.34,894.61)
  SIG 1 w4: 3890.46,850 3890.46,874.7 3909.34,893.58 v1(3909.34,894.61)
  SIG 1 w4.75: 3890.46,850 3904.9,835.56 3904.9,605 3949.9,560 4075.6,560 4140.36,624.76 4362.54,624.76 v1(4407.78,670)
AM263_ADC1_AIN2_SDFM0_D2: C92.1 J5/J7.67 U15.1 U15.10 U52.11 | length 926.3
  Top Layer w5.3: U52.11@4629.96,709.37 4897.79,709.37 4933.44,673.72 4933.44,574.11 4945.18,562.38 C92.1@4965,562.38 4965,540 4975,530 4988.59,530 4996.03,522.56 U15.10@4996.03,500.69 U15.1@4996.03,467.82 4996.03,440.53 4970.21,414.7 4865.21,414.7 4852.93,402.43 4756.6,402.43 J5/J7.67@4704.17,350
AM263_ADC1_AIN3: C97.1 D16.1 J1/J3.6 U1.V12 | length 3024.5
  Top Layer w4: U1.V12@3893.59,847.36 3905,835.95 3905,822.02 3911.16,815.87
  Top Layer w5.3: v1(2040,547.76) C97.1@2010,547.76 2010,485.62 D16.1@2010.51,485.1 2010.51,457.6 2028.08,440.03 2082.25,440.03 2151,371.28 2151,296.83 J1/J3.6@2104.17,250 ; v1(3668.01,260.08) 3681.78,246.32 3734.94,246.32 3783.62,295 3873.41,295 3951.58,373.17 3951.58,775.44 3911.16,815.87
  SIG 1 w4.75: v1(2040,547.76) 2122.99,464.77 3037,464.77 3105,396.77 3260.73,396.77 3325.5,332 3544.5,332 3616.42,260.08 v1(3668.01,260.08)
AM263_ADC1_AIN4: U1.U12
AM263_ADC1_AIN5: U1.R12
AM263_ADC2_AIN0: C74.1 J1/J3.25 U1.R10 U12.4 U12.7 | length 3359.5
  Top Layer w5.3: v1(1895,548.33) C74.1@1865,548.33 1865,514.79 1854.68,504.48 U12.7@1854.68,480.91 U12.4@1854.68,448.04 1854.68,422.25 1870,406.94 1947.24,406.94 J1/J3.25@2004.17,350
  Top Layer w10: U1.R10@3830.6,941.85 v1(3846.35,926.1)
  SIG 1 w4.75: v1(1895,548.33) 1914.25,567.58 2001,567.58 2030.03,596.6 2556.61,596.6 2601.75,641.74 2733.26,641.74 2776.52,685 3031.05,685 3060.94,714.89 3113.33,714.89 3129.56,698.66 v1(3275,698.66) ; v1(3835,363.27) 3807.77,390.5 3708.44,390.5 3682.23,416.7 3682.23,464.48 3783.89,566.14 3796.1,566.14 3832.75,602.79 3832.75,778.4 3815,796.15 3815,894.76 v1(3846.35,926.1)
  Bottom Layer w5.3: v1(3275,698.66) 3313.45,660.21 3313.45,543 3414.59,441.87 3448.13,441.87 3494,396 3802.27,396 v1(3835,363.27)
AM263_ADC2_AIN1: U1.T10 U52.38 | length 1470.1
  Top Layer w5.3: v1(4458.39,512.52) U52.38@4500.04,512.52
  Top Layer w10: U1.T10@3830.6,910.35 v1(3846.35,894.61)
  SIG 1 w4: v1(3846.35,894.61) 3847,893.95 3847,815.87
  SIG 1 w4.75: 3847,815.87 3847,799.35 3870.75,775.6 3870.75,579.71 3842.93,551.89 3791.41,551.89 3700.43,460.9 3700.43,426.71 3722.38,404.75 3825.52,404.75 3844.52,385.75 3955.25,385.75 4047.73,478.24 4343.24,478.24 4352.03,487.03 4432.9,487.03 v1(4458.39,512.52)
AM263_ADC2_AIN1_MCAN1_RX: C85.1 J5/J7.63 U14.1 U14.10 U52.4 | length 772.8
  Top Layer w5.3: J5/J7.63@4304.17,350 4374.17,420 4650.72,420 4698.4,467.68 U14.1@4785.63,467.68 U14.10@4785.63,500.55 4785.63,519.99 4774.59,531.03 4755.01,531.03 4747.11,538.93 C85.1@4747.11,561.53 4715.63,561.53 4705.59,571.57 U52.4@4629.96,571.57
